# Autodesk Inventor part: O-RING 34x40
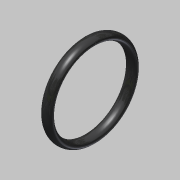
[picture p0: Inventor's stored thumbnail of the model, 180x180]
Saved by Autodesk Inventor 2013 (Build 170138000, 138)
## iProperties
Created: 2020-02
Part Number: O-RING 34x40
Material: 고무
Document SubType Name: Modeling
Designer: mduedu
Density: 1 g/cm^3
Author: mduedu
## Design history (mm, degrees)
sketch "스케치1"
  geometry: L1 (-3.29, 0)-(3.29, 0) reference; L2 (-2.35, 18.5)-(2.35, 18.5); L3 (0, 20)-(0, 17); 6 further points; 1 other entity
  constraints: 4 coincident, 4 end point, 2 horizontal, 2 midpoint, 1 vertical, 1 vertical alignment, 6 other
  dimensions: "d0" = 34 diameter of point (0, 17) L1; "d1" = 40 diameter of point (0, 20) L1; "d2" = 2.35 distance from line of point (2.35, 18.5) L3
revolve "회전1" sketch "스케치1" stored, may be unused: angle "d3" = 90 deg
node "솔리드1"
